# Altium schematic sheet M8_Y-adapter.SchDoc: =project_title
size Tabloid; PageSetup: Record=PageOptions¦CenterHorizontal=True¦CenterVertical=True¦PrintScale=0.73¦XCorrection=1.00¦YCorrection=1.00¦PrintKind=0¦BorderSize=5000000¦LeftOffset=0¦BottomOffset=0¦Orientation=2¦PaperLength=1000¦PaperWidth=1000¦Scale=100¦PaperSource=7¦PrintQuality=-4¦MediaType=1¦DitherType=10¦PaperKind=A4¦PrintScaleMode=1; CompanyName: Luxonis Holding; Organization: Luxonis Holding; Address1: 1925 Harmony Park Drive; Address2: Westminster, CO; Address3: 80234; Address4: United States; SheetNumber: 2; SheetTotal: 3
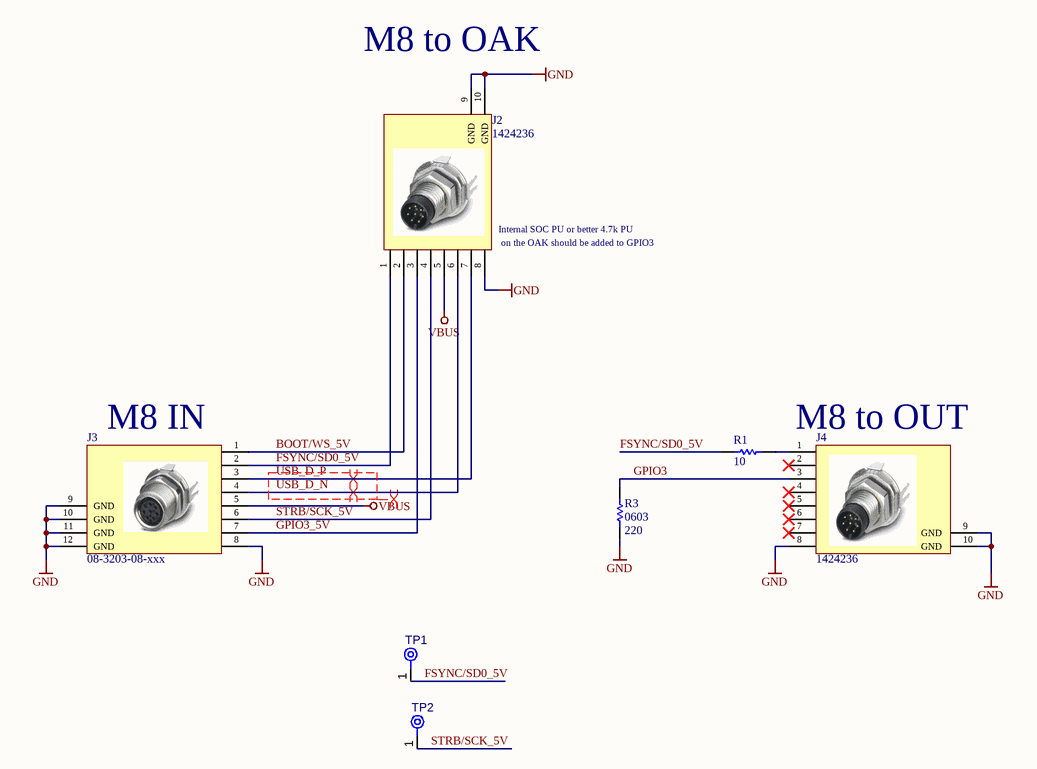
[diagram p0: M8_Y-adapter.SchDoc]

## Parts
J2  1424236  [1424236]
J3  08-3203-08-xxx  [08-3203-08-XXX]
J4  1424236  [1424236]
R1  value 10  [RESC0603(1608)_N]  (hidden comment: CRCW060310R0FKEA)
R3  value 220  Case/Package: 0603  [RESC0603(1608)_L]  (hidden comment: RC0603FR-07220RL)
TP1  TPAD6R  [TP06R]  (value not drawn)  (no BOM)
TP2  TPAD6R  [TP06R]  (value not drawn)  (no BOM)

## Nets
GND: J2.8 J2.9(GND) J2.10(GND) J3.8 J3.9(GND) J3.10(GND) J3.11(GND) J3.12(GND) J4.8 J4.9(GND) J4.10(GND) R3.1
VBUS: J2.5 J3.5
BOOT/WS_5V: J2.2 J3.1
FSYNC/SD0_5V: J2.1 J3.2 R1.1 TP1.1(TP)
GPIO3: J4.3 R3.2
GPIO3_5V: J2.3 J3.7
STRB/SCK_5V: J2.4 J3.6 TP2.1(TP)
USB_D_N: J2.6 J3.4
USB_D_P: J2.7 J3.3
NetJ4_1: J4.1 R1.2

Not connected (* = marked no-connect by the designer): J4 2* 4* 5* 6* 7*

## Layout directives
differential pair: USB_D_N, USB_D_P
rule Matched Net Lengths [Delay Tolerance = 1ps]; net class USB: USB_D_N, USB_D_P

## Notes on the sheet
- M8 to OAK
- (near J2) Internal SOC PU or better 4.7k PU
- (near J2) on the OAK should be added to GPIO3
- (near J3) M8 IN
- (near J4) M8 to OUT

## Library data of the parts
J2 J4 = CMP-002-00173-2: Circular Connector; Manufacturer 1: Phoenix Contact
J3 = CMP-002-00116-2: M8 Circular Connector; Manufacturer 1: KingTop
R1 = CMP-115-000012-5: RES SMD 10 OHM 1% 1/10W 0603; Manufacturer 1: Vishay; Temperature Coefficient: 100ppm/°C; Voltage Rating: 75V; Power Rating: 100mW
R3 = CMP-009-00346-1: RES SMD 220 OHM 1% 0.1W 0603; Manufacturer 1: Yageo; Power Rating: 100mW; Voltage Rating: 75V
TP1 TP2 = CMP-00028-00002-3: 0.6mm round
